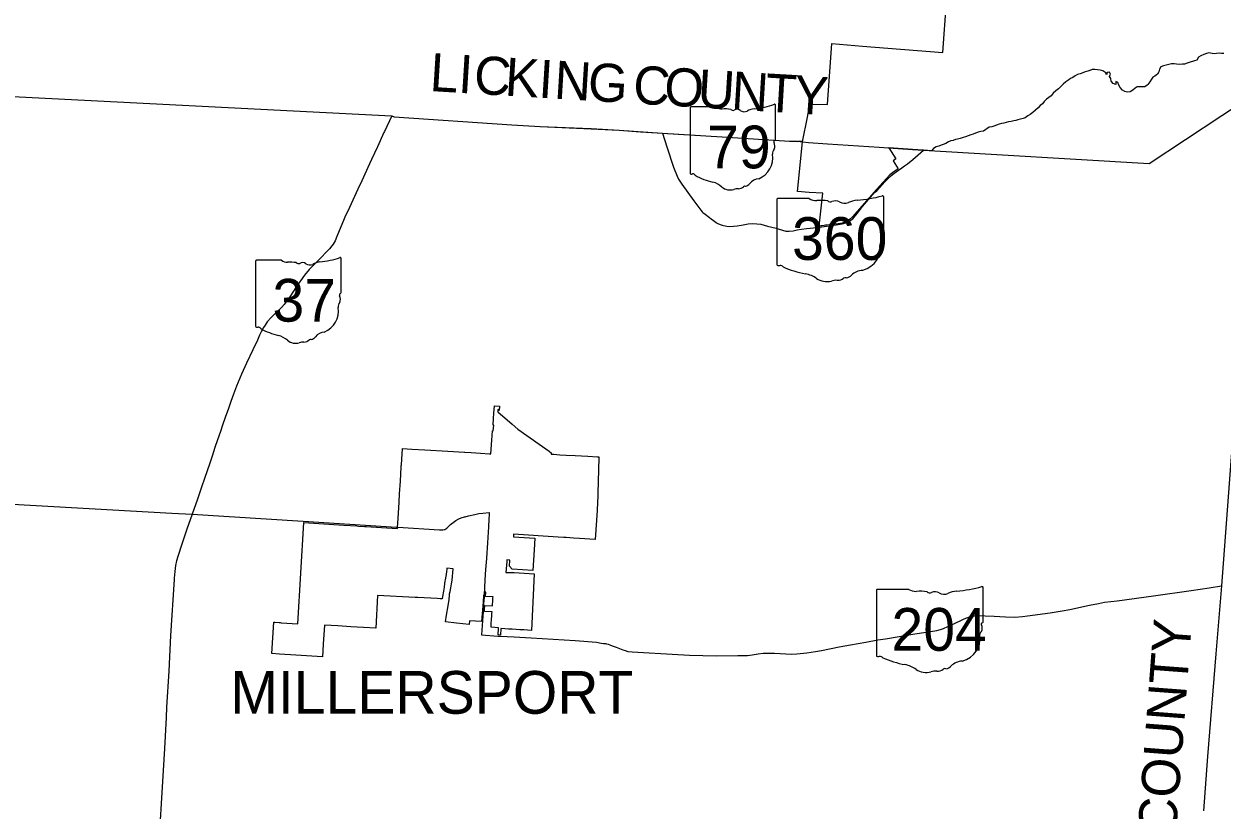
# Model space of a CAD drawing. Extents: x 1801177 to 2073177, y 551183 to 727183.
# Drawn here: x 1946535 to 1977949, y 684221 to 704837 of the extents above; entities that cross this region are included whole.
import ezdxf

# ---------------------------------------------------------------- set-up
doc = ezdxf.new("R2010")
doc.units = 0
for name, color, linetype in [('GM_X_Corporation', 7, 'Continuous'), ('GM_X_Corporation_Text', 7, 'Continuous'), ('GM_X_County', 7, 'Continuous'), ('GM_X_County_Text', 7, 'Continuous'), ('GM_X_State_Location', 7, 'Continuous'), ('GM_X_State_Route', 7, 'Continuous'), ('GM_X_State_Shield', 7, 'Continuous')]:
    doc.layers.add(name, color=color, linetype=linetype)

msp = doc.modelspace()

# ---------------------------------------------------------------- linework, layer by layer
at = {"layer": 'GM_X_Corporation'}
msp.add_lwpolyline([(1978000, 704064), (1977932, 704064), (1977876, 704068), (1977806, 704061), (1977746, 704053), (1977686, 704063), (1977606, 704079), (1977544, 704060), (1977474, 704038), (1977392, 704004), (1977336, 703962), (1977292, 703890), (1977228, 703867), (1977088, 703827), (1977034, 703809), (1976966, 703780), (1976908, 703782), (1976826, 703776), (1976757, 703780), (1976693, 703791), (1976623, 703789), (1976555, 703771), (1976483, 703759), (1976417, 703736), (1976345, 703712), (1976305, 703654), (1976291, 703586), (1976258, 703520), (1976190, 703470), (1976138, 703444), (1976098, 703386), (1976058, 703317), (1976004, 703251), (1975986, 703233), (1975928, 703191), (1975792, 703191), (1975722, 703186), (1975672, 703156), (1975606, 703100), (1975540, 703058), (1975470, 703049), (1975400, 703065), (1975336, 703103), (1975281, 703169), (1975245, 703234), (1975215, 703298), (1975161, 703324), (1975161, 703252), (1975093, 703278), (1975042, 703340), (1975034, 703403), (1974994, 703455), (1975026, 703519), (1975001, 703569), (1974935, 703565), (1974921, 703503), (1974903, 703559), (1974821, 703606), (1974755, 703624), (1974685, 703634), (1974618, 703640), (1974546, 703645), (1974480, 703621), (1974426, 703601), (1974364, 703583), (1974298, 703558), (1974228, 703532), (1974162, 703514), (1974100, 703474), (1974034, 703434), (1973978, 703405), (1973928, 703373), (1973850, 703319), (1973787, 703257), (1973723, 703197), (1973659, 703136), (1973591, 703084), (1973521, 703020), (1973467, 702956), (1973411, 702912), (1973347, 702862), (1973288, 702801), (1973238, 702739), (1973182, 702695), (1973126, 702639), (1973060, 702575), (1972992, 702517), (1972922, 702464), (1972858, 702424), (1972790, 702378), (1972736, 702360), (1972666, 702337), (1972598, 702321), (1972546, 702309), (1972494, 702295), (1972422, 702279), (1972352, 702268), (1972290, 702252), (1972226, 702238), (1972170, 702226), (1972106, 702211), (1972038, 702187), (1971968, 702161), (1971916, 702135), (1971840, 702133), (1971696, 702026), (1971622, 702018), (1971552, 702002), (1971486, 701977), (1971420, 701949), (1971366, 701933), (1971290, 701905), (1971222, 701880), (1971164, 701860), (1971084, 701836), (1971014, 701814), (1970960, 701803), (1970896, 701785), (1970842, 701769), (1970776, 701743), (1970708, 701705), (1970640, 701680), (1970588, 701658), (1970522, 701632), (1970456, 701612), (1970384, 701569), (1970327, 701510), (1970119, 701527), (1969837, 701546), (1969210, 701587), (1969396, 701302), (1969323, 701248), (1969459, 701039), (1969310, 700931), (1969239, 700878), (1968890, 700493), (1968381, 699919), (1968358, 699893), (1968335, 699867), (1968304, 699831), (1968273, 699796), (1968240, 699760), (1968208, 699730), (1968171, 699701), (1968143, 699682), (1968113, 699664), (1968074, 699646), (1968034, 699630), (1967989, 699616), (1967947, 699607), (1967882, 699598), (1967727, 699579), (1967588, 699562), (1967550, 699558), (1967519, 699554), (1967458, 699546), (1967426, 699543), (1967390, 699538), (1967478, 700396), (1967125, 700420), (1966820, 700440), (1966820, 700440), (1966949, 701742), (1967077, 702390), (1967145, 702736), (1967606, 702725), (1967720, 704321), (1968521, 704257), (1970628, 704088), (1970821, 706758)], dxfattribs=at)
msp.add_lwpolyline([(1959000, 694816), (1958992, 694702), (1958963, 694728), (1958959, 694665), (1959030, 694605), (1959209, 694451), (1959334, 694343), (1959488, 694210), (1960045, 693813), (1960304, 693629), (1960328, 693612), (1960357, 693591), (1960357, 693572), (1960356, 693555), (1960425, 693551), (1960590, 693541), (1960750, 693532), (1960988, 693518), (1961321, 693499), (1961576, 693483), (1961608, 693482), (1961607, 693462), (1961571, 692215), (1961568, 692156), (1961564, 692075), (1961516, 691319), (1961101, 691345), (1960947, 691355), (1960756, 691367), (1960721, 691369), (1960688, 691371), (1960541, 691380), (1959375, 691454), (1959371, 691384), (1959930, 691349), (1959913, 691049), (1959882, 690499), (1959338, 690534), (1959264, 690619), (1959275, 690774), (1959195, 690779), (1959192, 690742), (1959172, 690453), (1959385, 690449), (1959916, 690415), (1959839, 688931), (1959739, 688937), (1959640, 688943), (1959540, 688949), (1959440, 688955), (1959340, 688961), (1959240, 688968), (1959141, 688974), (1959041, 688980), (1959030, 688810), (1958970, 688814), (1958981, 688983), (1958982, 689004), (1958783, 689016), (1958788, 689103), (1958789, 689116), (1958796, 689216), (1958802, 689316), (1958806, 689376), (1958809, 689416), (1958609, 689428), (1958613, 689488), (1958619, 689588), (1958819, 689575), (1958823, 689642), (1958825, 689675), (1958832, 689775), (1958834, 689809), (1958635, 689823), (1958642, 689937), (1958612, 689939), (1958607, 689857), (1958582, 689858), (1958576, 689675), (1958536, 689165), (1958221, 689184), (1958211, 689088), (1957877, 689123), (1957586, 689153), (1957617, 689332), (1957660, 689576), (1957688, 689740), (1957694, 689854), (1957696, 689887), (1957708, 689953), (1957726, 690051), (1957744, 690150), (1957762, 690249), (1957772, 690348), (1957782, 690447), (1957793, 690547), (1957626, 690565), (1957625, 690556), (1957624, 690550), (1957623, 690546), (1957611, 690457), (1957604, 690414), (1957602, 690396), (1957596, 690358), (1957580, 690260), (1957574, 690224), (1957564, 690161), (1957549, 690062), (1957541, 690017), (1957533, 689963), (1957525, 689914), (1957517, 689865), (1957502, 689768), (1957501, 689766), (1957500, 689758), (1957450, 689761), (1957373, 689765), (1956867, 689791), (1956829, 689794), (1956792, 689796), (1955808, 689849), (1955759, 688988), (1955441, 689007), (1955103, 689028), (1954763, 689048), (1954413, 689070), (1954382, 688567), (1954362, 688243), (1953667, 688286), (1953234, 688312), (1953036, 688324), (1953085, 689147), (1953109, 689146), (1953229, 689138), (1953253, 689137), (1953283, 689135), (1953716, 689108), (1953875, 691761), (1954922, 691692), (1955261, 691671), (1955311, 691668), (1955461, 691659), (1955485, 691657), (1955510, 691656), (1955910, 691632), (1956327, 691605), (1956329, 691635), (1956344, 691870), (1956372, 692293), (1956385, 692512), (1956405, 692845), (1956428, 693215), (1956430, 693248), (1956432, 693278), (1956458, 693701), (1956709, 693685), (1957045, 693664), (1957645, 693630), (1958083, 693604), (1958087, 693604), (1958091, 693604), (1958095, 693604), (1958098, 693604), (1958261, 693594), (1958509, 693579), (1958738, 693566), (1958766, 693564), (1958780, 693563), (1958780, 693566), (1958805, 693922), (1958813, 694041), (1958822, 694166), (1958841, 694165), (1958854, 694314), (1958837, 694315), (1958849, 694500), (1958857, 694624), (1958864, 694736), (1958869, 694811), (1958870, 694824)], close=True, dxfattribs=at)
at = {"layer": 'GM_X_County'}
for points in [[(1945541, 702974), (1956176, 702427), (1956245, 702403), (1959325, 702195), (1960067, 702149), (1961404, 702092), (1962141, 702051), (1963273, 701974), (1964838, 701880), (1965937, 701808), (1966605, 701765), (1966648, 701765), (1966807, 701761), (1967104, 701729), (1967601, 701695), (1968963, 701604), (1969206, 701588), (1969837, 701546), (1970119, 701527), (1976042, 701178), (1978895, 703062)], [(1978334, 695468), (1977935, 690100), (1977782, 688320), (1977571, 685624), (1977464, 684196)]]:
    msp.add_lwpolyline(points, dxfattribs=at)
at = {"layer": 'GM_X_State_Route'}
for p, q in [((1962700, 702010), (1963274, 701972)), ((1951087, 692376), (1950945, 691984)), ((1950945, 691984), (1950808, 691583)), ((1958689, 691229), (1958661, 690831))]:
    msp.add_line(p, q, dxfattribs=at)
for points in [[(1956177, 702424), (1955985, 702017), (1955974, 701993)], [(1956177, 702424), (1956246, 702400), (1959326, 702192), (1960069, 702146), (1961405, 702089), (1962142, 702048), (1962700, 702010)], [(1955974, 701993), (1955804, 701616), (1955646, 701279), (1955595, 701167), (1955397, 700727), (1955286, 700507), (1955069, 700027), (1954951, 699771), (1954913, 699686), (1954801, 699413), (1954741, 699260), (1954692, 699148), (1954667, 699103), (1954640, 699065), (1954605, 699017), (1954543, 698940), (1954489, 698878), (1954306, 698690), (1954062, 698446), (1954017, 698398), (1953895, 698245), (1953788, 698100), (1953673, 697941), (1953618, 697859), (1953485, 697652), (1953356, 697477), (1953289, 697403), (1953145, 697269), (1953005, 697130), (1952914, 697027), (1952856, 696940), (1952813, 696873), (1952756, 696765), (1952715, 696672), (1952655, 696546), (1952538, 696293), (1952371, 695939), (1952236, 695649), (1952111, 695336), (1952031, 695128), (1951963, 694935), (1951896, 694750), (1951810, 694519), (1951737, 694315), (1951686, 694147), (1951609, 693934), (1951540, 693729), (1951471, 693504), (1951407, 693316)], [(1963274, 701972), (1963393, 701619), (1963568, 701084), (1963660, 700844), (1963695, 700770), (1963781, 700636), (1963943, 700415), (1964098, 700197), (1964285, 699952), (1964315, 699913), (1964338, 699889), (1964393, 699845), (1964509, 699763), (1964556, 699727), (1964616, 699682), (1964654, 699653), (1964685, 699631), (1964714, 699612), (1964745, 699596), (1964773, 699583), (1964794, 699574), (1964815, 699566), (1964845, 699557), (1964878, 699548), (1964919, 699540), (1964963, 699534), (1965045, 699527), (1965236, 699543), (1965351, 699557), (1965521, 699599), (1965628, 699607), (1965753, 699597), (1965858, 699584), (1965940, 699563), (1966034, 699535), (1966255, 699478), (1966337, 699453), (1966508, 699407), (1966602, 699399), (1966707, 699408), (1966812, 699435), (1966921, 699455), (1967053, 699476), (1967331, 699503), (1967832, 699568), (1967985, 699596), (1968087, 699619), (1968193, 699670), (1968269, 699727), (1968385, 699868), (1968523, 700048), (1968839, 700420), (1968898, 700460), (1969108, 700699), (1969165, 700758), (1969208, 700804), (1969249, 700838), (1969312, 700890), (1969402, 700961), (1969552, 701066), (1969622, 701117), (1969699, 701173), (1969844, 701286), (1970120, 701524)], [(1963274, 701972), (1964839, 701877), (1965938, 701805), (1966607, 701763), (1966649, 701762), (1966808, 701758), (1966834, 701760), (1966839, 701761)], [(1966839, 701761), (1966880, 701764), (1966939, 701770)], [(1951407, 693316), (1951268, 692912), (1951192, 692685), (1951087, 692376)], [(1939615, 692583), (1940345, 692545), (1943237, 692396), (1945021, 692303), (1946236, 692245), (1950416, 692011), (1950945, 691984), (1953853, 691799)], [(1953853, 691799), (1956307, 691643), (1956339, 691641)], [(1957720, 691706), (1957793, 691766), (1957855, 691812), (1957936, 691860), (1958001, 691885), (1958085, 691911), (1958102, 691915), (1958195, 691940), (1958353, 691975), (1958465, 691996), (1958569, 692011), (1958735, 692024)], [(1958735, 692024), (1958722, 691796), (1958717, 691699)], [(1950808, 691583), (1950677, 691197), (1950570, 690874), (1950534, 690754), (1950508, 690634), (1950487, 690478), (1950474, 690305)], [(1956339, 691641), (1957429, 691571), (1957519, 691573), (1957550, 691576), (1957568, 691581), (1957597, 691600), (1957620, 691617), (1957654, 691647), (1957720, 691706)], [(1958717, 691699), (1958714, 691647), (1958689, 691229)], [(1958661, 690831), (1958660, 690821), (1958637, 690528), (1958621, 690257), (1958604, 689853), (1958600, 689790)], [(1950474, 690305), (1950473, 690289), (1950471, 690268), (1950376, 688796), (1950332, 687859), (1950274, 686919), (1950263, 686647), (1950224, 685837), (1950018, 682517), (1950014, 682466)], [(1972512, 689279), (1972720, 689293), (1972849, 689312), (1973446, 689395), (1973758, 689442), (1973954, 689480), (1974475, 689598), (1974709, 689642), (1974871, 689670), (1975195, 689710), (1976154, 689835), (1977143, 689979), (1977608, 690051), (1977937, 690097)], [(1958597, 689741), (1958596, 689736), (1958580, 689486), (1958576, 689426), (1958536, 688812)], [(1958600, 689790), (1958599, 689785), (1958597, 689741)], [(1962062, 688490), (1962237, 688424), (1962301, 688402), (1962370, 688383), (1962485, 688371), (1962927, 688341), (1963230, 688324), (1963529, 688306), (1963983, 688285), (1964681, 688263), (1965255, 688271), (1965378, 688272), (1965506, 688276), (1965630, 688290), (1965787, 688319), (1965918, 688332), (1966213, 688332), (1966657, 688310), (1966802, 688318), (1967062, 688347), (1967289, 688382), (1967450, 688409), (1967908, 688499), (1968203, 688558), (1968607, 688628), (1968922, 688684), (1969121, 688715), (1969893, 688841), (1970193, 688888), (1970473, 688933), (1970570, 688958), (1970643, 688979), (1970760, 689031), (1970837, 689068), (1970968, 689129), (1971101, 689195), (1971184, 689232), (1971327, 689290), (1971369, 689303), (1971416, 689313), (1971460, 689317), (1971554, 689319), (1971739, 689314), (1971974, 689302), (1972269, 689287), (1972512, 689279)], [(1958536, 688812), (1958964, 688784), (1959025, 688780), (1959388, 688767), (1959835, 688737), (1960991, 688666), (1961550, 688621), (1961669, 688599)], [(1961669, 688599), (1961735, 688592), (1961784, 688585), (1961808, 688579), (1961856, 688567), (1961900, 688552), (1961962, 688528), (1962062, 688490)]]:
    msp.add_lwpolyline(points, dxfattribs=at)
at = {"layer": 'GM_X_State_Shield'}
for p, q in [((1964000, 702632), (1964000, 700931)), ((1964678, 702661), (1964022, 702661)), ((1966241, 701813), (1966241, 702703)), ((1966241, 701813), (1966241, 701813)), ((1966275, 700230), (1966275, 698529)), ((1967123, 700260), (1966303, 700260)), ((1969077, 699412), (1969077, 700302)), ((1969077, 699412), (1969077, 699412)), ((1954850, 697793), (1954850, 698683)), ((1952609, 698612), (1952609, 696910)), ((1953287, 698641), (1952631, 698641)), ((1954850, 697793), (1954850, 697793)), ((1968886, 689980), (1968886, 688278)), ((1969734, 690009), (1968914, 690009)), ((1971688, 689161), (1971688, 690051)), ((1971687, 689161), (1971688, 689161))]:
    msp.add_line(p, q, dxfattribs=at)
for centre, radius, start, end in [((1965443, 704980), 2377, 275.8445, 288.9065), ((1966216, 702707), 25, 351.8621, 97.738), ((1964025, 702635), 26, 98.1301, 188.1301), ((1964835, 702859), 252, 231.6195, 271.1119), ((1964918, 701706), 904, 80.4867, 94.9883), ((1965123, 702644), 72.7, 219.7921, 297.1024), ((1965230, 702448), 151, 54.4667, 119.1411), ((1965425, 702717), 182, 233.8562, 294.8282), ((1965746, 702141), 478, 97.3462, 120.7689), ((1966235, 701748), 38.6, 107.944, 210.337), ((1966214, 701810), 26.7, 289.6038, 7.7341), ((1966331, 701441), 169, 136.8065, 186.9296), ((1965990, 701635), 232, 340.033, 23.6496), ((1965576, 701328), 595, 292.3089, 8.9858), ((1964026, 700927), 26.2, 171.9584, 258.3066), ((1964030, 701101), 200, 267.339, 280.6039), ((1964071, 700832), 72.1, 29.7484, 93.2717), ((1964981, 702361), 1716, 240.4129, 257.1985), ((1964469, 700166), 537, 47.1842, 75.836), ((1965050, 700824), 341, 230.7004, 286.2918), ((1965272, 700697), 182, 268.777, 315.5493), ((1965436, 700532), 51.1, 65.7517, 132.6484), ((1965414, 700766), 192, 282.8732, 323.2771), ((1965827, 700453), 326, 94.4031, 142.5768), ((1965247, 700236), 280, 85.6951, 111.2099), ((1954052, 700960), 2377, 275.8445, 288.9065), ((1954825, 698687), 25, 351.8621, 97.738), ((1952634, 698615), 26, 98.1301, 188.1301), ((1953444, 698838), 252, 231.6195, 271.1119), ((1953527, 697686), 904, 80.4867, 94.9883), ((1953732, 698624), 72.7, 219.7921, 297.1024), ((1953839, 698427), 151, 54.4667, 119.1411), ((1954034, 698697), 182, 233.8562, 294.8282), ((1954355, 698121), 478, 97.3462, 120.7689), ((1954844, 697728), 38.6, 107.944, 210.337), ((1954599, 697615), 232, 340.033, 23.6496), ((1954823, 697790), 26.7, 289.6038, 7.7341), ((1954185, 697308), 595, 292.3089, 8.9858), ((1954940, 697421), 169, 136.8065, 186.9296), ((1952635, 696907), 26.2, 171.9584, 258.3066), ((1952639, 697081), 200, 267.339, 280.6039), ((1952680, 696812), 72.1, 29.7484, 93.2717), ((1953590, 698341), 1716, 240.4129, 257.1985), ((1954436, 696433), 326, 94.4031, 142.5768), ((1953078, 696146), 537, 47.1842, 75.836), ((1953659, 696804), 341, 230.7004, 286.2918), ((1953856, 696216), 280, 85.6951, 111.2099), ((1953881, 696677), 182, 268.777, 315.5493), ((1954045, 696512), 51.1, 65.7517, 132.6484), ((1954023, 696746), 192, 282.8732, 323.2771)]:
    msp.add_arc(centre, radius, start, end, dxfattribs=at)
for centre, major_axis, start_param, end_param in [((1966307, 700234), (32.5, 0), 1.712693, 3.28349), ((1967319, 700457), (315, 0), 4.042523, 4.731795), ((1968458, 699740), (598, 0), 1.699011, 2.107814), ((1968079, 702579), (2971, 0), 4.814394, 5.042369), ((1969046, 700305), (31.2, 0), 6.141152, 7.989035), ((1967423, 699304), (1130, 0), 1.404758, 1.657858), ((1967680, 700243), (90.8, 0), 3.836095, 5.185415), ((1967813, 700046), (189, 0), 0.950623, 2.079405), ((1968057, 700316), (227, 0), 4.081561, 5.145723), ((1969070, 699346), (48.3, 0), 1.883978, 3.671073), ((1968762, 699234), (290, 0), 5.934695, 6.695948), ((1969044, 699408), (33.4, 0), 5.05454, 6.418171), ((1968245, 698926), (743, 0), 5.101752, 6.440018), ((1969189, 699039), (211, 0), 2.387724, 3.262537), ((1966307, 698525), (32.7, 0), 3.00124, 4.508301), ((1966312, 698699), (250, 0), 4.665946, 4.897461), ((1966364, 698431), (90.1, 0), 0.519207, 1.627899), ((1967501, 699959), (2146, 0), 4.195997, 4.488961), ((1968559, 698051), (407, 0), 1.647645, 2.488434), ((1966861, 697765), (671, 0), 0.823519, 1.323587), ((1967588, 698423), (426, 0), 4.026481, 4.996735), ((1967834, 697834), (350, 0), 1.495662, 1.94098), ((1967865, 698295), (227, 0), 4.691044, 5.507374), ((1968070, 698130), (63.9, 0), 1.147584, 2.315152), ((1968043, 698364), (240, 0), 4.937069, 5.64225), ((1968918, 689983), (32.5, 0), 1.712693, 3.28349), ((1969929, 690206), (315, 0), 4.042523, 4.731795), ((1970034, 689054), (1130, 0), 1.404758, 1.657858), ((1970290, 689992), (90.8, 0), 3.836095, 5.185415), ((1970424, 689795), (189, 0), 0.950623, 2.079405), ((1970667, 690065), (227, 0), 4.081561, 5.145723), ((1971069, 689489), (598, 0), 1.699011, 2.107814), ((1970690, 692328), (2971, 0), 4.814394, 5.042369), ((1971657, 690055), (31.2, 0), 6.141152, 7.989035), ((1971799, 688789), (211, 0), 2.387724, 3.262537), ((1971680, 689096), (48.3, 0), 1.883978, 3.671073), ((1971373, 688983), (290, 0), 5.934695, 6.695948), ((1971654, 689158), (33.4, 0), 5.05454, 6.418171), ((1970856, 688676), (743, 0), 5.101752, 6.440018), ((1968918, 688275), (32.7, 0), 3.00124, 4.508301), ((1968923, 688449), (250, 0), 4.665946, 4.897461), ((1968974, 688180), (90.1, 0), 0.519207, 1.627899), ((1970112, 689709), (2146, 0), 4.195997, 4.488961), ((1969472, 687514), (671, 0), 0.823519, 1.323587), ((1970654, 688114), (240, 0), 4.937069, 5.64225), ((1971169, 687801), (407, 0), 1.647645, 2.488434), ((1970198, 688172), (426, 0), 4.026481, 4.996735), ((1970445, 687584), (350, 0), 1.495662, 1.94098), ((1970476, 688044), (227, 0), 4.691044, 5.507374), ((1970681, 687880), (63.9, 0), 1.147584, 2.315152)]:
    msp.add_ellipse(centre, major_axis=major_axis, ratio=0.8, start_param=start_param, end_param=end_param, dxfattribs=at)

# ---------------------------------------------------------------- texts
at = {"layer": 'GM_X_Corporation_Text'}
msp.add_text('MILLERSPORT', height=1120, rotation=0, dxfattribs=at).set_placement((1951946, 686747))
at = {"layer": 'GM_X_County_Text'}
for s, rotation, p in [('L', 356.5017, (1957159, 703080)), ('I', 356.5014, (1957905, 703034)), ('C', 356.5017, (1958314, 703009)), ('K', 356.5016, (1959126, 702960)), ('I', 356.5015, (1960009, 702906)), ('N', 356.5016, (1960418, 702881)), ('G', 356.5017, (1961300, 702827)), ('C', 356.5016, (1962486, 702754)), ('O', 356.5016, (1963299, 702705)), ('U', 356.5021, (1964181, 702651)), ('N', 356.5129, (1965064, 702597)), ('T', 356.6958, (1965951, 702543)), ('Y', 356.1453, (1966695, 702500)), ('FAIRFIELD COUNTY', 85.6692, (1976191, 676367))]:
    msp.add_text(s, height=1000, rotation=rotation, dxfattribs=at).set_placement(p)
at = {"layer": 'GM_X_State_Location'}
for s, p in [('s', (1964188, 701798)), ('r', (1964188, 701798)), ('s', (1968187, 699659)), ('r', (1968187, 699659)), ('s', (1970268, 688782)), ('r', (1970268, 688782))]:
    msp.add_text(s, height=1, dxfattribs=at).set_placement(p)
for s, p in [('79', (1963936, 701725)), ('360', (1967834, 699586)), ('204', (1969915, 688709))]:
    msp.add_text(s, height=1, rotation=0, dxfattribs=at).set_placement(p)
at = {"layer": 'GM_X_State_Shield'}
for s, p in [('79', (1964447, 701051)), ('360', (1966674, 698649)), ('37', (1953051, 697030)), ('204', (1969281, 688398))]:
    msp.add_text(s, height=1120.7, dxfattribs=at).set_placement(p)

doc.saveas('drawing.dxf')
